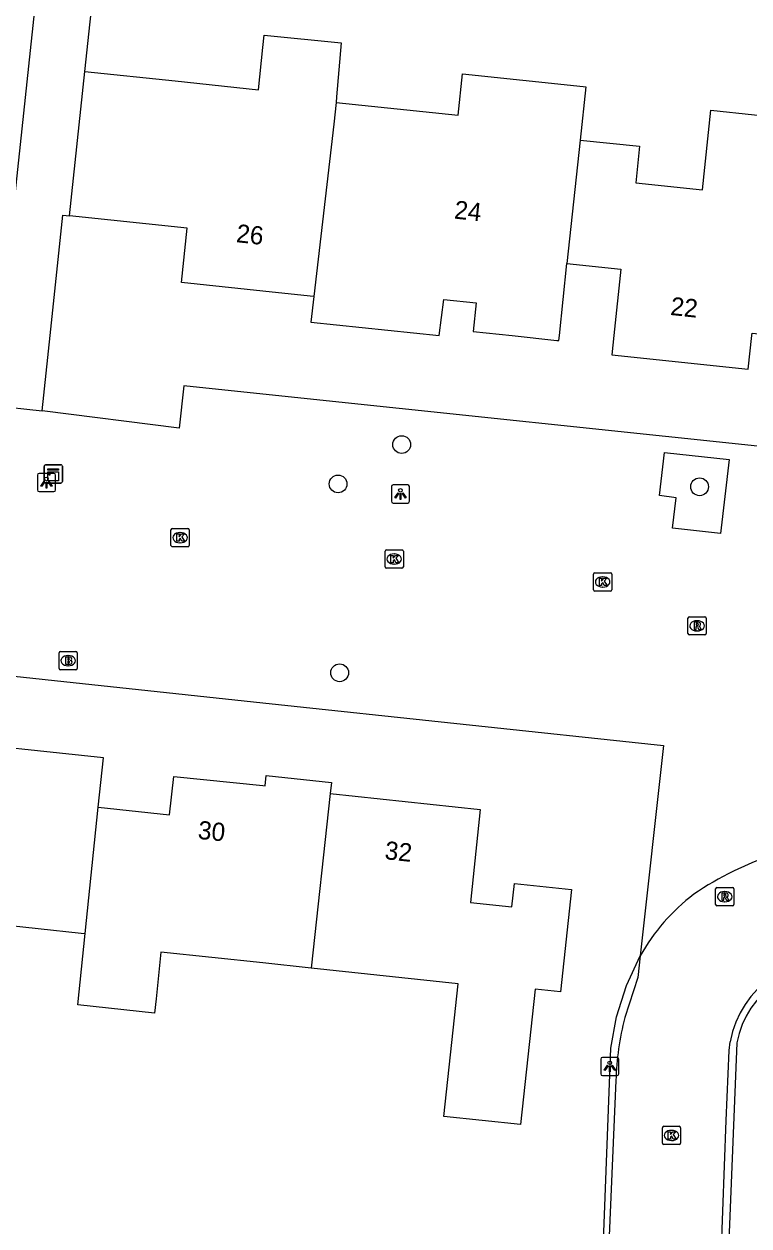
# Model space of a CAD drawing. Extents: x 162157 to 163165, y 378998 to 380775.
# Drawn here: x 162486.9 to 162526.7, y 380451 to 380517.1 of the extents above; entities that cross this region are included whole.
import ezdxf

# ---------------------------------------------------------------- set-up
doc = ezdxf.new("R2010")
doc.units = 0
for name, color, linetype in [('IMGEO_Boom', 7, 'Continuous'), ('IMGEO_Brandkraan', 7, 'Continuous'), ('IMGEO_Kast', 7, 'Continuous'), ('IMGEO_Kolk', 7, 'Continuous'), ('IMGEO_Lichtpunt', 7, 'Continuous'), ('IMGEO_Muur', 7, 'Continuous'), ('IMGEO_Pand', 7, 'Continuous'), ('IMGEO_Pand_nummerreeks', 7, 'Continuous'), ('IMGEO_Rijbaan_lokaal_open', 7, 'Continuous'), ('IMGEO_Rioolput', 7, 'Continuous'), ('IMGEO_Voetpad_open', 7, 'Continuous')]:
    doc.layers.add(name, color=color, linetype=linetype)

msp = doc.modelspace()

# ---------------------------------------------------------------- linework, layer by layer
at = {"layer": 'IMGEO_Boom'}
for centre in [(162507.634, 380494.009), (162504.135, 380491.843), (162524.023, 380491.687), (162504.219, 380481.456)]:
    msp.add_circle(centre, 0.489, dxfattribs=at)
at = {"layer": 'IMGEO_Brandkraan'}
for p, q in [((162488.785, 380481.696), (162488.785, 380482.548)), ((162488.86, 380482.622), (162489.712, 380482.622)), ((162489.273, 380482.402), (162489.298, 380482.402)), ((162489.786, 380482.548), (162489.786, 380481.696)), ((162489.712, 380481.622), (162488.86, 380481.622)), ((162489.296, 380481.842), (162489.271, 380481.842))]:
    msp.add_line(p, q, dxfattribs=at)
for points in [[(162488.785, 380481.696), (162488.785, 380482.548)], [(162488.86, 380482.622), (162489.712, 380482.622)], [(162489.133, 380482.322), (162489.133, 380481.922), (162489.346, 380481.922)], [(162489.364, 380482.322), (162489.133, 380482.322)], [(162489.312, 380482.241), (162489.258, 380482.241), (162489.258, 380482.165)], [(162489.258, 380482.165), (162489.311, 380482.165)], [(162489.786, 380482.548), (162489.786, 380481.696)], [(162489.712, 380481.622), (162488.86, 380481.622)], [(162489.32, 380482.089), (162489.258, 380482.089), (162489.258, 380482.008)], [(162489.258, 380482.008), (162489.32, 380482.008)]]:
    msp.add_lwpolyline(points, dxfattribs=at)
for centre, radius, start, end in [((162488.862, 380482.546), 0.0765, 91.55205, 178.44795), ((162488.862, 380482.546), 0.0765, 91.55205, 178.44795), ((162489.313, 380482.203), 0.0379, 267.82845, 90.93552), ((162489.368, 380482.177), 0.145, 59.4692, 91.53667), ((162489.393, 380482.224), 0.0922, 285.51372, 58.15012), ((162489.398, 380482.032), 0.105, 301.31148, 78.98903), ((162489.71, 380482.546), 0.0765, 1.55205, 88.44795), ((162489.71, 380482.546), 0.0765, 1.55205, 88.44795), ((162488.862, 380481.698), 0.0765, 181.55205, 268.44795), ((162488.862, 380481.698), 0.0765, 181.55205, 268.44795), ((162489.321, 380482.048), 0.0404, 269.87594, 90.50774), ((162489.352, 380482.173), 0.251, 268.66757, 293.53466), ((162489.71, 380481.698), 0.0765, 271.55205, 358.44795), ((162489.71, 380481.698), 0.0765, 271.55205, 358.44795)]:
    msp.add_arc(centre, radius, start, end, dxfattribs=at)
for centre, major_axis, ratio, start_param, end_param in [((162489.272, 380482.122), (-0.387, 0.002), 0.722429, 4.712389, 7.853982), ((162489.297, 380482.122), (-0.39, 0.002), 0.717154, 1.570796, 4.712389)]:
    msp.add_ellipse(centre, major_axis=major_axis, ratio=ratio, start_param=start_param, end_param=end_param, dxfattribs=at)
at = {"layer": 'IMGEO_Kast'}
for p, q in [((162487.965, 380491.968), (162487.965, 380492.809)), ((162487.965, 380492.809), (162487.965, 380491.968)), ((162488.04, 380492.893), (162488.881, 380492.893)), ((162488.881, 380492.893), (162488.04, 380492.893)), ((162488.965, 380492.818), (162488.965, 380491.977)), ((162488.965, 380491.977), (162488.965, 380492.818)), ((162488.89, 380491.893), (162488.049, 380491.893)), ((162488.049, 380491.893), (162488.89, 380491.893))]:
    msp.add_line(p, q, dxfattribs=at)
for points in [[(162488.16, 380492.683), (162488.76, 380492.683), (162488.76, 380492.598), (162488.16, 380492.598), (162488.16, 380492.683)], [(162488.16, 380492.508), (162488.76, 380492.508), (162488.76, 380492.019), (162488.16, 380492.019), (162488.16, 380492.508)]]:
    msp.add_lwpolyline(points, dxfattribs=at)
msp.add_circle((162488.244, 380492.357), 0.0377, dxfattribs=at)
for centre, start, end in [((162488.043, 380492.815), 92.4484, 184.28452), ((162488.043, 380492.815), 92.4484, 184.28452), ((162488.887, 380492.815), 2.4484, 94.28452), ((162488.887, 380492.815), 2.4484, 94.28452), ((162488.043, 380491.971), 182.4484, 274.28452), ((162488.043, 380491.971), 182.4484, 274.28452), ((162488.887, 380491.971), 272.4484, 4.28452), ((162488.887, 380491.971), 272.4484, 4.28452)]:
    msp.add_arc(centre, 0.0779, start, end, dxfattribs=at)
at = {"layer": 'IMGEO_Kolk'}
for p, q in [((162495.015, 380489.391), (162495.867, 380489.391)), ((162494.94, 380488.465), (162494.94, 380489.317)), ((162495.428, 380489.171), (162495.453, 380489.171)), ((162495.941, 380489.317), (162495.941, 380488.465)), ((162495.867, 380488.391), (162495.015, 380488.391)), ((162495.451, 380488.611), (162495.426, 380488.611)), ((162506.723, 380487.285), (162506.723, 380488.137)), ((162506.798, 380488.211), (162507.65, 380488.211)), ((162507.724, 380488.137), (162507.724, 380487.285)), ((162507.234, 380487.431), (162507.209, 380487.431)), ((162507.211, 380487.991), (162507.236, 380487.991)), ((162507.65, 380487.211), (162506.798, 380487.211)), ((162518.188, 380486.027), (162518.188, 380486.879)), ((162518.263, 380486.953), (162519.115, 380486.953)), ((162518.676, 380486.733), (162518.701, 380486.733)), ((162519.189, 380486.879), (162519.189, 380486.027)), ((162518.699, 380486.173), (162518.674, 380486.173)), ((162519.115, 380485.953), (162518.263, 380485.953)), ((162521.979, 380455.582), (162521.979, 380456.434)), ((162522.054, 380456.508), (162522.906, 380456.508)), ((162522.98, 380456.434), (162522.98, 380455.582)), ((162522.49, 380455.728), (162522.465, 380455.728)), ((162522.467, 380456.288), (162522.492, 380456.288)), ((162522.906, 380455.508), (162522.054, 380455.508))]:
    msp.add_line(p, q, dxfattribs=at)
for points in [[(162495.015, 380489.391), (162495.867, 380489.391)], [(162494.94, 380488.465), (162494.94, 380489.317)], [(162495.261, 380489.091), (162495.384, 380489.091), (162495.384, 380488.94), (162495.514, 380489.091), (162495.678, 380489.091), (162495.532, 380488.94), (162495.685, 380488.691), (162495.533, 380488.691), (162495.448, 380488.855), (162495.384, 380488.788), (162495.384, 380488.691), (162495.261, 380488.691), (162495.261, 380489.091)], [(162495.941, 380489.317), (162495.941, 380488.465)], [(162495.867, 380488.391), (162495.015, 380488.391)], [(162506.723, 380487.285), (162506.723, 380488.137)], [(162506.798, 380488.211), (162507.65, 380488.211)], [(162507.724, 380488.137), (162507.724, 380487.285)], [(162507.044, 380487.911), (162507.167, 380487.911), (162507.167, 380487.76), (162507.297, 380487.911), (162507.461, 380487.911), (162507.315, 380487.76), (162507.468, 380487.511), (162507.316, 380487.511), (162507.231, 380487.675), (162507.167, 380487.608), (162507.167, 380487.511), (162507.044, 380487.511), (162507.044, 380487.911)], [(162507.65, 380487.211), (162506.798, 380487.211)], [(162518.188, 380486.027), (162518.188, 380486.879)], [(162518.263, 380486.953), (162519.115, 380486.953)], [(162519.189, 380486.879), (162519.189, 380486.027)], [(162518.509, 380486.653), (162518.632, 380486.653), (162518.632, 380486.502), (162518.762, 380486.653), (162518.926, 380486.653), (162518.78, 380486.502), (162518.933, 380486.253), (162518.781, 380486.253), (162518.696, 380486.417), (162518.632, 380486.35), (162518.632, 380486.253), (162518.509, 380486.253), (162518.509, 380486.653)], [(162519.115, 380485.953), (162518.263, 380485.953)], [(162521.979, 380455.582), (162521.979, 380456.434)], [(162522.054, 380456.508), (162522.906, 380456.508)], [(162522.98, 380456.434), (162522.98, 380455.582)], [(162522.3, 380456.208), (162522.423, 380456.208), (162522.423, 380456.057), (162522.553, 380456.208), (162522.717, 380456.208), (162522.571, 380456.057), (162522.724, 380455.808), (162522.572, 380455.808), (162522.487, 380455.972), (162522.423, 380455.905), (162522.423, 380455.808), (162522.3, 380455.808), (162522.3, 380456.208)], [(162522.906, 380455.508), (162522.054, 380455.508)]]:
    msp.add_lwpolyline(points, dxfattribs=at)
for centre, start, end in [((162495.017, 380489.315), 91.55205, 178.44795), ((162495.017, 380489.315), 91.55205, 178.44795), ((162495.865, 380489.315), 1.55205, 88.44795), ((162495.865, 380489.315), 1.55205, 88.44795), ((162495.017, 380488.467), 181.55205, 268.44795), ((162495.017, 380488.467), 181.55205, 268.44795), ((162495.865, 380488.467), 271.55205, 358.44795), ((162495.865, 380488.467), 271.55205, 358.44795), ((162506.8, 380488.135), 91.55205, 178.44795), ((162506.8, 380488.135), 91.55205, 178.44795), ((162507.648, 380488.135), 1.55205, 88.44795), ((162507.648, 380488.135), 1.55205, 88.44795), ((162506.8, 380487.287), 181.55205, 268.44795), ((162506.8, 380487.287), 181.55205, 268.44795), ((162507.648, 380487.287), 271.55205, 358.44795), ((162507.648, 380487.287), 271.55205, 358.44795), ((162518.265, 380486.877), 91.55205, 178.44795), ((162518.265, 380486.877), 91.55205, 178.44795), ((162519.113, 380486.877), 1.55205, 88.44795), ((162519.113, 380486.877), 1.55205, 88.44795), ((162518.265, 380486.029), 181.55205, 268.44795), ((162518.265, 380486.029), 181.55205, 268.44795), ((162519.113, 380486.029), 271.55205, 358.44795), ((162519.113, 380486.029), 271.55205, 358.44795), ((162522.056, 380456.432), 91.55205, 178.44795), ((162522.056, 380456.432), 91.55205, 178.44795), ((162522.904, 380456.432), 1.55205, 88.44795), ((162522.904, 380456.432), 1.55205, 88.44795), ((162522.056, 380455.584), 181.55205, 268.44795), ((162522.056, 380455.584), 181.55205, 268.44795), ((162522.904, 380455.584), 271.55205, 358.44795), ((162522.904, 380455.584), 271.55205, 358.44795)]:
    msp.add_arc(centre, 0.0765, start, end, dxfattribs=at)
for centre, major_axis, ratio, start_param, end_param in [((162495.427, 380488.891), (-0.387, 0.002), 0.722429, 4.712389, 7.853982), ((162495.452, 380488.891), (-0.39, 0.002), 0.717154, 1.570796, 4.712389), ((162507.21, 380487.711), (-0.387, 0.002), 0.722429, 4.712389, 7.853982), ((162507.235, 380487.711), (-0.39, 0.002), 0.717154, 1.570796, 4.712389), ((162518.675, 380486.453), (-0.387, 0.002), 0.722429, 4.712389, 7.853982), ((162518.7, 380486.453), (-0.39, 0.002), 0.717154, 1.570796, 4.712389), ((162522.466, 380456.008), (-0.387, 0.002), 0.722429, 4.712389, 7.853982), ((162522.491, 380456.008), (-0.39, 0.002), 0.717154, 1.570796, 4.712389)]:
    msp.add_ellipse(centre, major_axis=major_axis, ratio=ratio, start_param=start_param, end_param=end_param, dxfattribs=at)
at = {"layer": 'IMGEO_Lichtpunt'}
for p, q in [((162487.592, 380492.325), (162487.592, 380491.518)), ((162487.592, 380492.325), (162487.592, 380491.518)), ((162488.494, 380492.42), (162487.686, 380492.42)), ((162488.494, 380492.42), (162487.686, 380492.42)), ((162488.588, 380491.518), (162488.588, 380492.325)), ((162488.588, 380491.518), (162488.588, 380492.325)), ((162487.686, 380491.424), (162488.494, 380491.424)), ((162487.686, 380491.424), (162488.494, 380491.424)), ((162507.066, 380491.695), (162507.066, 380490.888)), ((162507.066, 380491.695), (162507.066, 380490.888)), ((162507.968, 380491.79), (162507.16, 380491.79)), ((162507.968, 380491.79), (162507.16, 380491.79)), ((162508.062, 380490.888), (162508.062, 380491.695)), ((162508.062, 380490.888), (162508.062, 380491.695)), ((162507.16, 380490.794), (162507.968, 380490.794)), ((162507.16, 380490.794), (162507.968, 380490.794)), ((162519.483, 380460.299), (162518.675, 380460.299)), ((162519.483, 380460.299), (162518.675, 380460.299)), ((162518.581, 380460.204), (162518.581, 380459.397)), ((162518.581, 380460.204), (162518.581, 380459.397)), ((162519.577, 380459.397), (162519.577, 380460.204)), ((162519.577, 380459.397), (162519.577, 380460.204)), ((162518.675, 380459.303), (162519.483, 380459.303)), ((162518.675, 380459.303), (162519.483, 380459.303))]:
    msp.add_line(p, q, dxfattribs=at)
for points in [[(162487.966, 380491.989), (162488.005, 380491.961), (162487.817, 380491.699), (162487.779, 380491.726), (162487.966, 380491.989)], [(162488.068, 380491.941), (162488.115, 380491.941), (162488.115, 380491.619), (162488.068, 380491.619), (162488.068, 380491.941)], [(162488.178, 380491.961), (162488.216, 380491.988), (162488.403, 380491.726), (162488.364, 380491.698), (162488.178, 380491.961)], [(162507.44, 380491.359), (162507.479, 380491.331), (162507.291, 380491.069), (162507.253, 380491.096), (162507.44, 380491.359)], [(162507.542, 380491.311), (162507.589, 380491.311), (162507.589, 380490.989), (162507.542, 380490.989), (162507.542, 380491.311)], [(162507.652, 380491.331), (162507.69, 380491.358), (162507.877, 380491.096), (162507.838, 380491.068), (162507.652, 380491.331)], [(162518.955, 380459.868), (162518.994, 380459.84), (162518.806, 380459.578), (162518.768, 380459.605), (162518.955, 380459.868)], [(162519.057, 380459.82), (162519.104, 380459.82), (162519.104, 380459.498), (162519.057, 380459.498), (162519.057, 380459.82)], [(162519.167, 380459.84), (162519.205, 380459.867), (162519.392, 380459.605), (162519.353, 380459.577), (162519.167, 380459.84)]]:
    msp.add_lwpolyline(points, dxfattribs=at)
for centre in [(162488.091, 380492.123), (162507.565, 380491.493), (162519.08, 380460.002)]:
    msp.add_circle(centre, 0.0994, dxfattribs=at)
for centre, start, end in [((162487.686, 380492.325), 90, 180), ((162487.686, 380492.325), 90, 180), ((162488.494, 380492.325), 0, 90), ((162488.494, 380492.325), 0, 90), ((162487.686, 380491.518), 180, 270), ((162487.686, 380491.518), 180, 270), ((162488.494, 380491.518), 270, 0), ((162488.494, 380491.518), 270, 360), ((162507.16, 380491.695), 90, 180), ((162507.16, 380491.695), 90, 180), ((162507.968, 380491.695), 0, 90), ((162507.968, 380491.695), 0, 90), ((162507.16, 380490.888), 180, 270), ((162507.16, 380490.888), 180, 270), ((162507.968, 380490.888), 270, 0), ((162507.968, 380490.888), 270, 360), ((162518.675, 380460.204), 90, 180), ((162518.675, 380460.204), 90, 180), ((162519.483, 380460.204), 0, 90), ((162519.483, 380460.204), 0, 90), ((162518.675, 380459.397), 180, 270), ((162518.675, 380459.397), 180, 270), ((162519.483, 380459.397), 270, 0), ((162519.483, 380459.397), 270, 360)]:
    msp.add_arc(centre, 0.0946, start, end, dxfattribs=at)
at = {"layer": 'IMGEO_Muur'}
msp.add_lwpolyline([(162490.197, 380514.538), (162491.375, 380525.475)], dxfattribs=at)
at = {"layer": 'IMGEO_Pand'}
for points in [[(162490.197, 380514.538), (162495.17, 380514.013), (162499.754, 380513.529), (162500, 380515.86), (162500.071, 380516.537), (162504.298, 380516.106), (162504.053, 380513.133), (162504.021, 380512.834)], [(162517.457, 380510.76), (162520.719, 380510.416), (162520.507, 380508.407), (162524.187, 380508.019), (162524.649, 380512.397), (162529.447, 380511.891), (162529.796, 380515.192), (162531.963, 380514.964), (162531.615, 380511.662), (162530.602, 380502.062)], [(162489.359, 380506.6), (162490.197, 380514.538)], [(162504.021, 380512.834), (162510.734, 380512.126), (162510.973, 380514.4), (162517.614, 380513.7), (162517.766, 380513.684), (162517.457, 380510.76)], [(162504.021, 380512.834), (162503.895, 380511.641), (162502.802, 380502.157)], [(162517.457, 380510.76), (162516.727, 380503.965)], [(162502.802, 380502.157), (162502.596, 380502.179), (162500, 380502.453), (162495.512, 380502.927), (162495.827, 380505.917), (162489.359, 380506.6)], [(162502.802, 380502.157), (162502.639, 380500.745), (162509.7, 380500), (162509.948, 380501.995), (162511.738, 380501.806), (162511.572, 380500.225), (162513.708, 380500), (162516.166, 380499.741), (162516.281, 380499.729), (162516.309, 380500), (162516.727, 380503.965)], [(162516.727, 380503.965), (162519.682, 380503.654), (162519.296, 380500), (162519.185, 380498.949), (162526.698, 380498.15), (162526.895, 380500), (162526.909, 380500.134), (162528.144, 380500), (162530.302, 380499.766)], [(162490.943, 380474.06), (162491.225, 380476.786), (162481.884, 380477.774), (162481.722, 380476.24), (162478.647, 380476.565)], [(162490.943, 380474.06), (162494.866, 380473.645), (162495.09, 380475.759), (162500, 380475.251), (162500.115, 380475.239), (162500.175, 380475.801), (162503.768, 380475.417), (162503.703, 380474.824)], [(162503.703, 380474.824), (162511.958, 380473.942), (162511.41, 380468.82), (162513.697, 380468.575), (162513.836, 380469.87), (162516.969, 380469.535), (162516.367, 380463.908), (162514.972, 380464.057), (162514.175, 380456.606), (162509.952, 380457.057), (162510.46, 380461.803), (162510.732, 380464.348), (162502.651, 380465.21)], [(162503.703, 380474.824), (162502.651, 380465.21)], [(162490.224, 380467.116), (162490.943, 380474.06)], [(162477.486, 380466.256), (162477.365, 380465.177), (162480.789, 380464.815), (162480.921, 380466.068), (162485.036, 380465.632), (162485.249, 380467.643), (162489.999, 380467.14), (162490.224, 380467.116)], [(162502.651, 380465.21), (162500, 380465.493), (162494.391, 380466.092), (162494.119, 380463.519), (162494.036, 380462.737), (162489.816, 380463.183), (162490.224, 380467.116)]]:
    msp.add_lwpolyline(points, dxfattribs=at)
at = {"layer": 'IMGEO_Rijbaan_lokaal_open'}
for points in [[(162529.653, 380493.665), (162500, 380496.775), (162495.643, 380497.232), (162495.383, 380494.912), (162487.858, 380495.873)], [(162485.141, 380496.162), (162487.858, 380495.873)], [(162522.728, 380491.08), (162521.813, 380491.217), (162522.099, 380493.567), (162525.655, 380493.184), (162525.171, 380489.118), (162522.529, 380489.403), (162522.728, 380491.08)], [(162483.564, 380481.564), (162483.722, 380481.547), (162500, 380479.806), (162522.027, 380477.451), (162520.752, 380465.884)], [(162516.524, 380406.414), (162517.286, 380412.125), (162519.136, 380460.805), (162519.454, 380462.537), (162519.997, 380464.252), (162520.752, 380465.884)], [(162520.752, 380465.884), (162520.62, 380464.691), (162519.904, 380462.486)], [(162522.92, 380405.75), (162523.435, 380409.422), (162523.692, 380411.661), (162523.76, 380414.096), (162523.979, 380419.44), (162524.178, 380423.229), (162524.437, 380430.106), (162524.904, 380440.743), (162525.123, 380446.851), (162525.49, 380456.829), (162525.64, 380460.683), (162525.696, 380461.163)], [(162526.069, 380461.094), (162524.071, 380411.634), (162523.269, 380405.705)], [(162519.414, 380459.03), (162518.867, 380446.216), (162518.391, 380431.687), (162517.884, 380419.349), (162517.665, 380412.096), (162517.383, 380409.796), (162516.918, 380406.359)]]:
    msp.add_lwpolyline(points, dxfattribs=at)
for centre, radius, start, end in [((162533.838, 380454.359), 18.033, 108.19445, 124.17942), ((162530.497, 380460.381), 11.191, 127.35028, 150.54381), ((162531.296, 380460.083), 5.703, 81.07861, 169.08552), ((162531.296, 380460.083), 5.324, 81.05111, 169.05351), ((162536.018, 380458.439), 16.614, 165.9003, 177.96021)]:
    msp.add_arc(centre, radius, start, end, dxfattribs=at)
at = {"layer": 'IMGEO_Rioolput'}
for p, q in [((162523.381, 380483.613), (162523.381, 380484.465)), ((162523.456, 380484.539), (162524.308, 380484.539)), ((162523.869, 380484.319), (162523.894, 380484.319)), ((162524.382, 380484.465), (162524.382, 380483.613)), ((162524.308, 380483.539), (162523.456, 380483.539)), ((162523.892, 380483.759), (162523.867, 380483.759)), ((162524.903, 380468.715), (162524.903, 380469.567)), ((162524.978, 380469.641), (162525.83, 380469.641)), ((162525.904, 380469.567), (162525.904, 380468.715)), ((162525.391, 380469.421), (162525.416, 380469.421)), ((162525.83, 380468.641), (162524.978, 380468.641)), ((162525.414, 380468.861), (162525.389, 380468.861))]:
    msp.add_line(p, q, dxfattribs=at)
for points in [[(162523.381, 380483.613), (162523.381, 380484.465)], [(162523.456, 380484.539), (162524.308, 380484.539)], [(162523.97, 380484.237), (162523.718, 380484.239), (162523.718, 380483.839)], [(162523.896, 380484.158), (162523.842, 380484.158), (162523.842, 380484.077)], [(162524.382, 380484.465), (162524.382, 380483.613)], [(162524.308, 380483.539), (162523.456, 380483.539)], [(162523.718, 380483.839), (162523.842, 380483.839), (162523.842, 380484.001), (162523.853, 380484.001)], [(162523.842, 380484.077), (162523.894, 380484.077)], [(162523.9, 380483.972), (162523.971, 380483.839), (162524.111, 380483.839), (162524.046, 380483.965)], [(162524.903, 380468.715), (162524.903, 380469.567)], [(162524.978, 380469.641), (162525.83, 380469.641)], [(162525.904, 380469.567), (162525.904, 380468.715)], [(162525.492, 380469.339), (162525.24, 380469.341), (162525.24, 380468.941)], [(162525.24, 380468.941), (162525.364, 380468.941), (162525.364, 380469.103), (162525.375, 380469.103)], [(162525.418, 380469.26), (162525.364, 380469.26), (162525.364, 380469.179)], [(162525.364, 380469.179), (162525.416, 380469.179)], [(162525.422, 380469.074), (162525.493, 380468.941), (162525.633, 380468.941), (162525.568, 380469.067)], [(162525.83, 380468.641), (162524.978, 380468.641)]]:
    msp.add_lwpolyline(points, dxfattribs=at)
for centre, radius, start, end in [((162523.458, 380484.463), 0.0765, 91.55205, 178.44795), ((162523.458, 380484.463), 0.0765, 91.55205, 178.44795), ((162523.902, 380484.062), 0.0964, 77.00612, 93.18647), ((162523.916, 380484.119), 0.0378, 276.66336, 79.67722), ((162523.969, 380484.127), 0.109, 350.36119, 89.41601), ((162523.967, 380484.127), 0.112, 277.58423, 350.98172), ((162524.306, 380484.463), 0.0765, 1.55205, 88.44795), ((162524.306, 380484.463), 0.0765, 1.55205, 88.44795), ((162523.458, 380483.615), 0.0765, 181.55205, 268.44795), ((162523.458, 380483.615), 0.0765, 181.55205, 268.44795), ((162523.852, 380483.948), 0.0533, 26.02933, 88.69889), ((162523.878, 380484.266), 0.19, 274.7715, 282.96867), ((162523.951, 380483.912), 0.108, 29.51342, 73.79051), ((162524.306, 380483.615), 0.0765, 271.55205, 358.44795), ((162524.306, 380483.615), 0.0765, 271.55205, 358.44795), ((162524.98, 380469.565), 0.0765, 91.55205, 178.44795), ((162524.98, 380469.565), 0.0765, 91.55205, 178.44795), ((162525.828, 380469.565), 0.0765, 1.55205, 88.44795), ((162525.828, 380469.565), 0.0765, 1.55205, 88.44795), ((162525.374, 380469.05), 0.0533, 26.02933, 88.69889), ((162525.4, 380469.368), 0.19, 274.7715, 282.96867), ((162525.424, 380469.164), 0.0964, 77.00612, 93.18647), ((162525.438, 380469.221), 0.0378, 276.66336, 79.67722), ((162525.491, 380469.229), 0.109, 350.36119, 89.41601), ((162525.489, 380469.229), 0.112, 277.58423, 350.98172), ((162525.473, 380469.014), 0.108, 29.51342, 73.79051), ((162524.98, 380468.717), 0.0765, 181.55205, 268.44795), ((162524.98, 380468.717), 0.0765, 181.55205, 268.44795), ((162525.828, 380468.717), 0.0765, 271.55205, 358.44795), ((162525.828, 380468.717), 0.0765, 271.55205, 358.44795)]:
    msp.add_arc(centre, radius, start, end, dxfattribs=at)
for centre, major_axis, ratio, start_param, end_param in [((162523.868, 380484.039), (-0.387, 0.002), 0.722429, 4.712389, 7.853982), ((162523.893, 380484.039), (-0.39, 0.002), 0.717154, 1.570796, 4.712389), ((162525.39, 380469.141), (-0.387, 0.002), 0.722429, 4.712389, 7.853982), ((162525.415, 380469.141), (-0.39, 0.002), 0.717154, 1.570796, 4.712389)]:
    msp.add_ellipse(centre, major_axis=major_axis, ratio=ratio, start_param=start_param, end_param=end_param, dxfattribs=at)
at = {"layer": 'IMGEO_Voetpad_open'}
for points in [[(162490.197, 380514.538), (162491.375, 380525.475), (162493.667, 380546.763), (162494.84, 380557.651), (162500, 380560.947), (162503.119, 380562.939)], [(162485.141, 380496.162), (162485.549, 380500), (162489.731, 380539.305)], [(162487.858, 380495.873), (162488.29, 380500), (162488.985, 380506.63), (162489.359, 380506.6)]]:
    msp.add_lwpolyline(points, dxfattribs=at)

# ---------------------------------------------------------------- texts
at = {"layer": 'IMGEO_Pand_nummerreeks'}
for s, rotation, p in [('24', 353.98394, (162510.492, 380506.443)), ('26', 353.97248, (162498.498, 380505.146)), ('22', 353.92947, (162522.384, 380501.143)), ('30', 354.09281, (162496.389, 380472.327)), ('32', 353.90373, (162506.666, 380471.208))]:
    msp.add_text(s, height=1, rotation=rotation, dxfattribs=at).set_placement(p)

doc.saveas('drawing.dxf')
